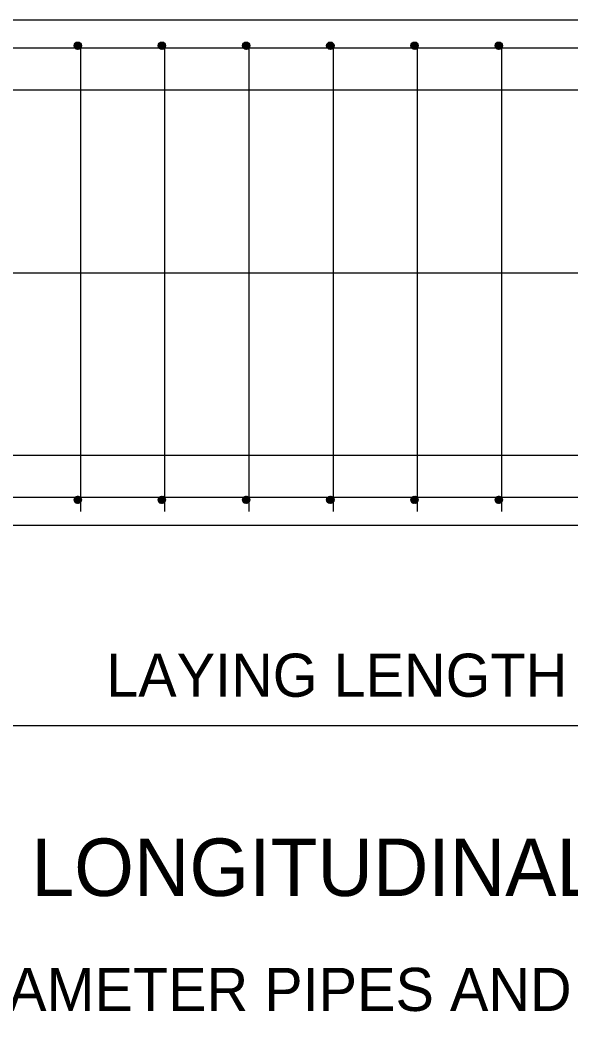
# Model space of a CAD drawing. Extents: x 49991.4 to 50021, y 49987.6 to 50011.4.
# Drawn here: x 50010.185 to 50010.952, y 49993.48 to 49994.877 of the extents above; entities that cross this region are included whole.
import ezdxf

# ---------------------------------------------------------------- set-up
doc = ezdxf.new("R2010")
doc.units = 0
for name, color, linetype in [('Level 1', 7, 'Continuous'), ('Level 2', 7, 'Continuous'), ('Level 3', 7, 'Continuous'), ('Level 5', 7, 'Continuous')]:
    doc.layers.add(name, color=color, linetype=linetype)

msp = doc.modelspace()

# ---------------------------------------------------------------- linework, layer by layer
at = {"layer": 'Level 1'}
for p, q in [((50011.5389, 49994.8774), (50009.7605, 49994.8774)), ((50011.4393, 49994.8384), (50009.9169, 49994.8384)), ((50010.2687, 49994.8384), (50010.2687, 49994.1934)), ((50010.3859, 49994.8384), (50010.3859, 49994.1934)), ((50010.5031, 49994.8384), (50010.5031, 49994.1934)), ((50010.6204, 49994.8384), (50010.6204, 49994.1934)), ((50010.7377, 49994.8384), (50010.7377, 49994.1934)), ((50010.8549, 49994.8384), (50010.8549, 49994.1934)), ((50011.6367, 49994.7798), (50009.8583, 49994.7798)), ((50011.6367, 49994.2716), (50009.8583, 49994.2716)), ((50011.4393, 49994.213), (50009.9169, 49994.213)), ((50011.5389, 49994.1739), (50009.7605, 49994.1739))]:
    msp.add_line(p, q, dxfattribs=at)
for points in [[(50010.2597, 49994.8414), (50010.2653, 49994.8469)], [(50010.2598, 49994.8422), (50010.2645, 49994.8469)], [(50010.2599, 49994.8406), (50010.266, 49994.8468)], [(50010.2599, 49994.8432), (50010.2634, 49994.8467)], [(50010.2601, 49994.84), (50010.2666, 49994.8466)], [(50010.2603, 49994.8394), (50010.2672, 49994.8464)], [(50010.2607, 49994.8389), (50010.2677, 49994.846)], [(50010.2608, 49994.8449), (50010.2617, 49994.8458), (50010.2618, 49994.8458)], [(50010.2609, 49994.8384), (50010.261, 49994.8384), (50010.2682, 49994.8457), (50010.2683, 49994.8457)], [(50010.2614, 49994.838), (50010.2614, 49994.838), (50010.2686, 49994.8452), (50010.2686, 49994.8452)], [(50010.2619, 49994.8376), (50010.2689, 49994.8448)], [(50010.2623, 49994.8373), (50010.2693, 49994.8442)], [(50010.377, 49994.8414), (50010.3825, 49994.8469)], [(50010.3771, 49994.8422), (50010.3817, 49994.8469)], [(50010.3771, 49994.8406), (50010.3833, 49994.8468)], [(50010.3772, 49994.8432), (50010.3807, 49994.8467)], [(50010.3773, 49994.84), (50010.3839, 49994.8466)], [(50010.3776, 49994.8394), (50010.3845, 49994.8464)], [(50010.3779, 49994.8389), (50010.3849, 49994.846)], [(50010.3781, 49994.8449), (50010.3789, 49994.8458), (50010.3791, 49994.8458)], [(50010.3782, 49994.8384), (50010.3783, 49994.8384), (50010.3855, 49994.8457), (50010.3855, 49994.8457)], [(50010.3787, 49994.838), (50010.3787, 49994.838), (50010.3859, 49994.8452), (50010.3859, 49994.8452)], [(50010.3791, 49994.8376), (50010.3862, 49994.8448)], [(50010.3796, 49994.8373), (50010.3866, 49994.8442)], [(50010.4943, 49994.8422), (50010.4989, 49994.8469)], [(50010.4943, 49994.8414), (50010.4997, 49994.8469)], [(50010.4943, 49994.8406), (50010.5005, 49994.8468)], [(50010.4945, 49994.8432), (50010.4979, 49994.8467)], [(50010.4945, 49994.84), (50010.5011, 49994.8466)], [(50010.4949, 49994.8394), (50010.5017, 49994.8464)], [(50010.4951, 49994.8389), (50010.5023, 49994.846)], [(50010.4953, 49994.8449), (50010.4962, 49994.8458), (50010.4963, 49994.8458)], [(50010.4955, 49994.8384), (50010.4955, 49994.8384), (50010.5027, 49994.8457), (50010.5027, 49994.8457)], [(50010.4959, 49994.838), (50010.4959, 49994.838), (50010.5031, 49994.8452), (50010.5031, 49994.8452)], [(50010.4963, 49994.8376), (50010.5035, 49994.8448)], [(50010.4969, 49994.8373), (50010.5039, 49994.8442)], [(50010.6115, 49994.8422), (50010.6162, 49994.8469)], [(50010.6115, 49994.8414), (50010.617, 49994.8469)], [(50010.6117, 49994.8406), (50010.6177, 49994.8468)], [(50010.6117, 49994.8432), (50010.6152, 49994.8467)], [(50010.6118, 49994.84), (50010.6184, 49994.8466)], [(50010.6121, 49994.8394), (50010.619, 49994.8464)], [(50010.6124, 49994.8389), (50010.6195, 49994.846)], [(50010.6125, 49994.8449), (50010.6135, 49994.8458), (50010.6135, 49994.8458)], [(50010.6127, 49994.8384), (50010.6127, 49994.8384), (50010.6199, 49994.8457), (50010.62, 49994.8457)], [(50010.6131, 49994.838), (50010.6131, 49994.838), (50010.6204, 49994.8452), (50010.6204, 49994.8452)], [(50010.6136, 49994.8376), (50010.6207, 49994.8448)], [(50010.6141, 49994.8373), (50010.6211, 49994.8442)], [(50010.7287, 49994.8414), (50010.7343, 49994.8469)], [(50010.7288, 49994.8422), (50010.7335, 49994.8469)], [(50010.7289, 49994.8406), (50010.735, 49994.8468)], [(50010.7289, 49994.8432), (50010.7325, 49994.8467)], [(50010.7291, 49994.84), (50010.7357, 49994.8466)], [(50010.7293, 49994.8394), (50010.7363, 49994.8464)], [(50010.7297, 49994.8389), (50010.7367, 49994.846)], [(50010.7298, 49994.8449), (50010.7307, 49994.8458), (50010.7308, 49994.8458)], [(50010.73, 49994.8384), (50010.73, 49994.8384), (50010.7372, 49994.8457), (50010.7373, 49994.8457)], [(50010.7304, 49994.838), (50010.7304, 49994.838), (50010.7377, 49994.8452), (50010.7377, 49994.8452)], [(50010.7309, 49994.8376), (50010.738, 49994.8448)], [(50010.7314, 49994.8373), (50010.7383, 49994.8442)], [(50010.846, 49994.8414), (50010.8515, 49994.8469)], [(50010.8461, 49994.8422), (50010.8507, 49994.8469)], [(50010.8461, 49994.8406), (50010.8523, 49994.8468)], [(50010.8462, 49994.8432), (50010.8497, 49994.8467)], [(50010.8463, 49994.84), (50010.8529, 49994.8466)], [(50010.8466, 49994.8394), (50010.8535, 49994.8464)], [(50010.8469, 49994.8389), (50010.854, 49994.846)], [(50010.8471, 49994.8449), (50010.8479, 49994.8458), (50010.8481, 49994.8458)], [(50010.8473, 49994.8384), (50010.8473, 49994.8384), (50010.8545, 49994.8457), (50010.8545, 49994.8457)], [(50010.8477, 49994.838), (50010.8477, 49994.838), (50010.8549, 49994.8452), (50010.8549, 49994.8452)], [(50010.8481, 49994.8376), (50010.8553, 49994.8448)], [(50010.8487, 49994.8373), (50010.8556, 49994.8442)], [(50010.2629, 49994.837), (50010.2696, 49994.8437)], [(50010.2635, 49994.8368), (50010.2698, 49994.8431)], [(50010.2643, 49994.8367), (50010.2699, 49994.8424)], [(50010.2651, 49994.8367), (50010.2699, 49994.8416)], [(50010.266, 49994.8368), (50010.2699, 49994.8406)], [(50010.2673, 49994.8373), (50010.2693, 49994.8393)], [(50010.3801, 49994.837), (50010.3869, 49994.8437)], [(50010.3808, 49994.8368), (50010.3871, 49994.8431)], [(50010.3815, 49994.8367), (50010.3871, 49994.8424)], [(50010.3823, 49994.8367), (50010.3872, 49994.8416)], [(50010.3833, 49994.8368), (50010.3871, 49994.8406)], [(50010.3846, 49994.8373), (50010.3866, 49994.8393)], [(50010.4974, 49994.837), (50010.5041, 49994.8437)], [(50010.4981, 49994.8368), (50010.5043, 49994.8431)], [(50010.4987, 49994.8367), (50010.5044, 49994.8424)], [(50010.4995, 49994.8367), (50010.5045, 49994.8416)], [(50010.5005, 49994.8368), (50010.5043, 49994.8406)], [(50010.5019, 49994.8373), (50010.5039, 49994.8393)], [(50010.6147, 49994.837), (50010.6213, 49994.8437)], [(50010.6153, 49994.8368), (50010.6215, 49994.8431)], [(50010.616, 49994.8367), (50010.6217, 49994.8424)], [(50010.6169, 49994.8367), (50010.6217, 49994.8416)], [(50010.6177, 49994.8368), (50010.6216, 49994.8406)], [(50010.6191, 49994.8373), (50010.6211, 49994.8393)], [(50010.7319, 49994.837), (50010.7386, 49994.8437)], [(50010.7325, 49994.8368), (50010.7388, 49994.8431)], [(50010.7333, 49994.8367), (50010.7389, 49994.8424)], [(50010.7341, 49994.8367), (50010.7389, 49994.8416)], [(50010.735, 49994.8368), (50010.7389, 49994.8406)], [(50010.7363, 49994.8373), (50010.7383, 49994.8393)], [(50010.8492, 49994.837), (50010.8559, 49994.8437)], [(50010.8498, 49994.8368), (50010.8561, 49994.8431)], [(50010.8505, 49994.8367), (50010.8562, 49994.8424)], [(50010.8513, 49994.8367), (50010.8562, 49994.8416)], [(50010.8523, 49994.8368), (50010.8561, 49994.8406)], [(50010.8536, 49994.8373), (50010.8556, 49994.8393)], [(50010.2597, 49994.21), (50010.2653, 49994.2045)], [(50010.2598, 49994.2092), (50010.2645, 49994.2045)], [(50010.2599, 49994.2108), (50010.266, 49994.2046)], [(50010.2599, 49994.2082), (50010.2634, 49994.2047)], [(50010.2601, 49994.2114), (50010.2666, 49994.2048)], [(50010.2603, 49994.212), (50010.2672, 49994.205)], [(50010.2607, 49994.2125), (50010.2677, 49994.2054)], [(50010.2608, 49994.2065), (50010.2617, 49994.2056), (50010.2618, 49994.2056)], [(50010.2609, 49994.213), (50010.261, 49994.213), (50010.2682, 49994.2057), (50010.2683, 49994.2057)], [(50010.2614, 49994.2134), (50010.2614, 49994.2134), (50010.2686, 49994.2062), (50010.2686, 49994.2062)], [(50010.2619, 49994.2138), (50010.2689, 49994.2066)], [(50010.2623, 49994.2141), (50010.2693, 49994.2072)], [(50010.2629, 49994.2144), (50010.2696, 49994.2077)], [(50010.2635, 49994.2146), (50010.2698, 49994.2083)], [(50010.2643, 49994.2147), (50010.2699, 49994.209)], [(50010.2651, 49994.2147), (50010.2699, 49994.2098)], [(50010.266, 49994.2146), (50010.2699, 49994.2108)], [(50010.2673, 49994.2141), (50010.2693, 49994.2121)], [(50010.377, 49994.21), (50010.3825, 49994.2045)], [(50010.3771, 49994.2108), (50010.3833, 49994.2046)], [(50010.3771, 49994.2092), (50010.3817, 49994.2045)], [(50010.3772, 49994.2082), (50010.3807, 49994.2047)], [(50010.3773, 49994.2114), (50010.3839, 49994.2048)], [(50010.3776, 49994.212), (50010.3845, 49994.205)], [(50010.3779, 49994.2125), (50010.3849, 49994.2054)], [(50010.3781, 49994.2065), (50010.3789, 49994.2056), (50010.3791, 49994.2056)], [(50010.3782, 49994.213), (50010.3783, 49994.213), (50010.3855, 49994.2057), (50010.3855, 49994.2057)], [(50010.3787, 49994.2134), (50010.3787, 49994.2134), (50010.3859, 49994.2062), (50010.3859, 49994.2062)], [(50010.3791, 49994.2138), (50010.3862, 49994.2066)], [(50010.3796, 49994.2141), (50010.3866, 49994.2072)], [(50010.3801, 49994.2144), (50010.3869, 49994.2077)], [(50010.3808, 49994.2146), (50010.3871, 49994.2083)], [(50010.3815, 49994.2147), (50010.3871, 49994.209)], [(50010.3823, 49994.2147), (50010.3872, 49994.2098)], [(50010.3833, 49994.2146), (50010.3871, 49994.2108)], [(50010.3846, 49994.2141), (50010.3866, 49994.2121)], [(50010.4943, 49994.2108), (50010.5005, 49994.2046)], [(50010.4943, 49994.21), (50010.4997, 49994.2045)], [(50010.4943, 49994.2092), (50010.4989, 49994.2045)], [(50010.4945, 49994.2114), (50010.5011, 49994.2048)], [(50010.4945, 49994.2082), (50010.4979, 49994.2047)], [(50010.4949, 49994.212), (50010.5017, 49994.205)], [(50010.4951, 49994.2125), (50010.5023, 49994.2054)], [(50010.4953, 49994.2065), (50010.4962, 49994.2056), (50010.4963, 49994.2056)], [(50010.4955, 49994.213), (50010.4955, 49994.213), (50010.5027, 49994.2057), (50010.5027, 49994.2057)], [(50010.4959, 49994.2134), (50010.4959, 49994.2134), (50010.5031, 49994.2062), (50010.5031, 49994.2062)], [(50010.4963, 49994.2138), (50010.5035, 49994.2066)], [(50010.4969, 49994.2141), (50010.5039, 49994.2072)], [(50010.4974, 49994.2144), (50010.5041, 49994.2077)], [(50010.4981, 49994.2146), (50010.5043, 49994.2083)], [(50010.4987, 49994.2147), (50010.5044, 49994.209)], [(50010.4995, 49994.2147), (50010.5045, 49994.2098)], [(50010.5005, 49994.2146), (50010.5043, 49994.2108)], [(50010.5019, 49994.2141), (50010.5039, 49994.2121)], [(50010.6115, 49994.21), (50010.617, 49994.2045)], [(50010.6115, 49994.2092), (50010.6162, 49994.2045)], [(50010.6117, 49994.2108), (50010.6177, 49994.2046)], [(50010.6117, 49994.2082), (50010.6152, 49994.2047)], [(50010.6118, 49994.2114), (50010.6184, 49994.2048)], [(50010.6121, 49994.212), (50010.619, 49994.205)], [(50010.6124, 49994.2125), (50010.6195, 49994.2054)], [(50010.6125, 49994.2065), (50010.6135, 49994.2056), (50010.6135, 49994.2056)], [(50010.6127, 49994.213), (50010.6127, 49994.213), (50010.6199, 49994.2057), (50010.62, 49994.2057)], [(50010.6131, 49994.2134), (50010.6131, 49994.2134), (50010.6204, 49994.2062), (50010.6204, 49994.2062)], [(50010.6136, 49994.2138), (50010.6207, 49994.2066)], [(50010.6141, 49994.2141), (50010.6211, 49994.2072)], [(50010.6147, 49994.2144), (50010.6213, 49994.2077)], [(50010.6153, 49994.2146), (50010.6215, 49994.2083)], [(50010.616, 49994.2147), (50010.6217, 49994.209)], [(50010.6169, 49994.2147), (50010.6217, 49994.2098)], [(50010.6177, 49994.2146), (50010.6216, 49994.2108)], [(50010.6191, 49994.2141), (50010.6211, 49994.2121)], [(50010.7287, 49994.21), (50010.7343, 49994.2045)], [(50010.7288, 49994.2092), (50010.7335, 49994.2045)], [(50010.7289, 49994.2108), (50010.735, 49994.2046)], [(50010.7289, 49994.2082), (50010.7325, 49994.2047)], [(50010.7291, 49994.2114), (50010.7357, 49994.2048)], [(50010.7293, 49994.212), (50010.7363, 49994.205)], [(50010.7297, 49994.2125), (50010.7367, 49994.2054)], [(50010.7298, 49994.2065), (50010.7307, 49994.2056), (50010.7308, 49994.2056)], [(50010.73, 49994.213), (50010.73, 49994.213), (50010.7372, 49994.2057), (50010.7373, 49994.2057)], [(50010.7304, 49994.2134), (50010.7304, 49994.2134), (50010.7377, 49994.2062), (50010.7377, 49994.2062)], [(50010.7309, 49994.2138), (50010.738, 49994.2066)], [(50010.7314, 49994.2141), (50010.7383, 49994.2072)], [(50010.7319, 49994.2144), (50010.7386, 49994.2077)], [(50010.7325, 49994.2146), (50010.7388, 49994.2083)], [(50010.7333, 49994.2147), (50010.7389, 49994.209)], [(50010.7341, 49994.2147), (50010.7389, 49994.2098)], [(50010.735, 49994.2146), (50010.7389, 49994.2108)], [(50010.7363, 49994.2141), (50010.7383, 49994.2121)], [(50010.846, 49994.21), (50010.8515, 49994.2045)], [(50010.8461, 49994.2108), (50010.8523, 49994.2046)], [(50010.8461, 49994.2092), (50010.8507, 49994.2045)], [(50010.8462, 49994.2082), (50010.8497, 49994.2047)], [(50010.8463, 49994.2114), (50010.8529, 49994.2048)], [(50010.8466, 49994.212), (50010.8535, 49994.205)], [(50010.8469, 49994.2125), (50010.854, 49994.2054)], [(50010.8471, 49994.2065), (50010.8479, 49994.2056), (50010.8481, 49994.2056)], [(50010.8473, 49994.213), (50010.8473, 49994.213), (50010.8545, 49994.2057), (50010.8545, 49994.2057)], [(50010.8477, 49994.2134), (50010.8477, 49994.2134), (50010.8549, 49994.2062), (50010.8549, 49994.2062)], [(50010.8481, 49994.2138), (50010.8553, 49994.2066)], [(50010.8487, 49994.2141), (50010.8556, 49994.2072)], [(50010.8492, 49994.2144), (50010.8559, 49994.2077)], [(50010.8498, 49994.2146), (50010.8561, 49994.2083)], [(50010.8505, 49994.2147), (50010.8562, 49994.209)], [(50010.8513, 49994.2147), (50010.8562, 49994.2098)], [(50010.8523, 49994.2146), (50010.8561, 49994.2108)], [(50010.8536, 49994.2141), (50010.8556, 49994.2121)]]:
    msp.add_lwpolyline(points, dxfattribs=at)
for centre in [(50010.2649, 49994.8418), (50010.3821, 49994.8418), (50010.4994, 49994.8418), (50010.6166, 49994.8418), (50010.7339, 49994.8418), (50010.8511, 49994.8418), (50010.2649, 49994.2097), (50010.3821, 49994.2097), (50010.4994, 49994.2097), (50010.6166, 49994.2097), (50010.7339, 49994.2097), (50010.8511, 49994.2097)]:
    msp.add_circle(centre, 0.00512, dxfattribs=at)
at = {"layer": 'Level 3'}
msp.add_line((50009.7605, 49993.8956), (50011.5389, 49993.8956), dxfattribs=at)
at = {"layer": 'Level 5'}
msp.add_line((50009.6605, 49994.5257), (50011.7367, 49994.5257), dxfattribs=at)

# ---------------------------------------------------------------- texts
at = {"layer": 'Level 2'}
for s, height, p in [('LAYING LENGTH', 0.06, (50010.3045, 49993.9356)), ('TYPICAL LONGITUDINAL SECTION', 0.08, (50009.7248, 49993.6583)), ('33" [825] DIAMETER PIPES AND SMALLER', 0.06, (50009.7469, 49993.4983))]:
    msp.add_text(s, height=height, dxfattribs=at).set_placement(p)

doc.saveas('drawing.dxf')
